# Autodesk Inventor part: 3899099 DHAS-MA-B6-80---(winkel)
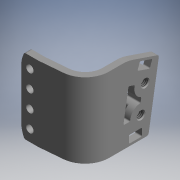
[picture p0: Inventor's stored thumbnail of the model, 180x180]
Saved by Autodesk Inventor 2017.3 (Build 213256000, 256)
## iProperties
Part Number: 3899099 DHAS-MA-B6-80---(winkel)
Material: Generic
Catalog Web Link: www.cadenas.de
Description: DHAS-MA_w-bracket
Vendor: FESTO
Document SubType Name: Modeling
Designer: partserver
Manufacturer: FESTO
Mass: 5.29381 g
Surface Area: 44.3897 cm^2
Volume: 5.29381 cm^3
Density: 1 g/cm^3
Appearance: PSOLRGB-175-175-175
Category: PARTsolutions
Company: FESTO
Title: 3899099 DHAS-MA-B6-80---(winkel)
Author: Cadenas PARTsolutions
Comments: bracket
PSOL_IDENT_0: {$CADENAS_DATA\23d-libs\festo\parts\d\dhas\parts\dhas_ma_winkel.prj},208 {VTYP=3D},{NB=3899099 DHAS-
PSOL_IDENT_1: MA-B6-80---(winkel)},{LINA=3899099 DHAS-MA-B6-80---(winkel)},{NN=DHAS-MA_w},{DATE=30.08.2019 14:48:2
PSOL_IDENT_2: 6},{GEOMDATE=01.09.2017 11:45:00},{VERSION=},{LINEID=230},{WBVAR=},{WBNUMERIC=}  {NB=3899099 DHAS-MA
PSOL_IDENT_3: -B6-80---(winkel)},{LINA=3899099 DHAS-MA-B6-80---(winkel)},{KT=DUMMY},{TNR=3899099},{TYP=DHAS-MA-B6-
PSOL_IDENT_4: 80},{SIZE=80}
NB: 3899099 DHAS-MA-B6-80---(winkel)
NN: DHAS-MA_w
NT: bracket
NBSYN: $TNR. $TYP.---(winkel)
LINA: 3899099 DHAS-MA-B6-80---(winkel)
CATALOG: Festo
TNR: 3899099
TYP: DHAS-MA-B6-80
SIZE: 80
SUPPLIER: FESTO
ARTICLENO: 3899099 DHAS-MA-B6-80---(winkel)
BOMINFO: 3899099 DHAS-MA-B6-80---(winkel)
CREATOR: CADENAS GmbH
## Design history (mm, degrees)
sketch "Sketch_3"
  geometry: L1 (0, 1.811)-(20.7, 0); L2 (20.7, 0)-(28.6, 0); L3 (28.6, 0)-(28.6, 3); L4 (28.6, 3)-(20.7, 3); L5 (20.7, 3)-(3, 4.549); L6 (3, 4.549)-(3, 35); L7 (3, 35)-(0, 35); L8 (0, 35)-(0, 1.811)
  constraints: 16 end point
extrude "Extrusion1" join sketch "Sketch_3" distance "d0" = 34.5; taper "d1" = 0 deg
sketch "Sketch_2"
  geometry: L1 (0, 1.811)-(20.7, 0); L2 (20.7, 0)-(28.6, 0); L3 (28.6, 0)-(28.6, 3); L4 (28.6, 3)-(21.049, 3); L5 (20.352, 3.03)-(10.303, 3.91); L6 (3, 11.879)-(3, 35); L7 (3, 35)-(0, 35); L8 (0, 35)-(0, 1.811); A1 r 8 centre (21.049, 11) between (20.352, 3.03) and (21.049, 3); A2 r 8 centre (11, 11.879) between (3, 11.879) and (10.303, 3.91)
  constraints: 16 end point, 4 point on circle, 2 centre point
extrude "Extrusion2" join sketch "Sketch_2" distance "d2" = 34.5; taper "d3" = 0 deg
sketch "Sketch_4"
  geometry: L1 (-5, -5)-(35, -5); L2 (35, -5)-(35, 45); L3 (35, 45)-(-5, 45); L4 (-5, 45)-(-5, -5); L5 (10.041, 0.933)-(20.222, 0.042); L6 (21.18, 0)-(28.6, 0); L7 (28.6, 0)-(28.6, 3); L8 (28.6, 3)-(21.049, 3); L9 (20.352, 3.03)-(10.303, 3.91); L10 (3, 11.879)-(3, 35); L11 (3, 35)-(0, 35); L12 (0, 35)-(0, 11.891); A1 r 11 centre (11, 11.891) between (0, 11.891) and (10.041, 0.933); A2 r 11 centre (21.18, 11) between (20.222, 0.042) and (21.18, 0); A3 r 8 centre (21.049, 11) between (20.352, 3.03) and (21.049, 3); A4 r 8 centre (11, 11.879) between (3, 11.879) and (10.303, 3.91)
  constraints: 24 end point, 8 point on circle, 4 centre point
extrude "Extrusion3" cut sketch "Sketch_4" distance "d4" = 48; taper "d5" = 0 deg
sketch "Sketch_5"
  geometry: L1 (45, 55)-(-5, 55); L2 (-5, 55)-(-5, -5); L3 (-5, -5)-(45, -5); L4 (45, -5)-(45, 55); L5 (29.252, 34.5)-(0, 34.5); L6 (0, 34.5)-(0, 0); L7 (0, 0)-(18.13, 0); L8 (22.939, 0.792)-(34.195, 4.602); L9 (34.861, 5.712)-(30.238, 33.663); A1 r 15 centre (18.13, 15) between (18.13, 0) and (22.939, 0.792); A2 r 1 centre (33.875, 5.549) between (34.195, 4.602) and (34.861, 5.712); A3 r 1 centre (29.252, 33.5) between (30.238, 33.663) and (29.252, 34.5)
  constraints: 18 end point, 6 point on circle, 3 centre point
extrude "Extrusion4" cut sketch "Sketch_5" distance "d6" = 3; taper "d7" = 0 deg
sketch "Sketch_6"
  geometry: L1 (5, 53)-(-35, 53); L2 (-35, 53)-(-35, -5); L3 (-35, -5)-(5, -5); L4 (5, -5)-(5, 53); L5 (0, 34.5)-(-26.483, 34.5); L6 (-28.6, 28.5)-(-28.6, 6); L7 (-26.483, 0)-(0, 0); L8 (0, 0)-(0, 34.5); A1 r 1 centre (-26.483, 33.5) between (-26.483, 34.5) and (-27.388, 33.926); A2 r 12.75 centre (-15.85, 28.5) between (-27.388, 33.926) and (-28.6, 28.5); A3 r 12.75 centre (-15.85, 6) between (-28.6, 6) and (-27.388, 0.574); A4 r 1 centre (-26.483, 1) between (-27.388, 0.574) and (-26.483, 0)
  constraints: 16 end point, 8 point on circle, 4 centre point
extrude "Extrusion5" cut sketch "Sketch_6" distance "d8" = 3; taper "d9" = 0 deg
sketch "Sketch6"
  geometry: 1 further point
hole "Hole1" sketch "Sketch6" at (3.42, 29.25) diameter "d10" = 3.4; stored, may be unused: countersink angle "d14" = 90 deg, drill point angle "d16" = 0 deg; dims "d11" = 6, "d12" = 4, "d13" = 2, "d15" = 3
pattern_linear "Rectangular Pattern1" dims "d19" = 8, "d22" = 0
sketch "Sketch_10"
  geometry: L1 (30.244, 8.053)-(25.51, 6.442); L2 (25.198, 5.808)-(26.003, 3.441); L3 (26.638, 3.129)-(31.371, 4.74); L4 (31.683, 5.374)-(30.878, 7.741); A1 r 0.5 centre (30.405, 7.58) between (30.878, 7.741) and (30.244, 8.053); A2 r 0.5 centre (25.671, 5.969) between (25.51, 6.442) and (25.198, 5.808); A3 r 0.5 centre (26.477, 3.602) between (26.003, 3.441) and (26.638, 3.129); A4 r 0.5 centre (31.21, 5.213) between (31.371, 4.74) and (31.683, 5.374)
  constraints: 8 end point, 8 point on circle, 4 centre point
extrude "Extrusion6" cut sketch "Sketch_10" distance "d23" = 3; taper "d24" = 0 deg
sketch "Sketch_18"
  geometry: L1 (21.121, 32.96)-(21.121, 30.46); L2 (21.621, 29.96)-(26.621, 29.959); L3 (27.121, 30.459)-(27.121, 32.959); L4 (26.621, 33.459)-(21.621, 33.46); A1 r 0.5 centre (21.621, 32.96) between (21.621, 33.46) and (21.121, 32.96); A2 r 0.5 centre (21.621, 30.46) between (21.121, 30.46) and (21.621, 29.96); A3 r 0.5 centre (26.621, 30.459) between (26.621, 29.959) and (27.121, 30.459); A4 r 0.5 centre (26.621, 32.959) between (27.121, 32.959) and (26.621, 33.459)
  constraints: 8 end point, 8 point on circle, 4 centre point
extrude "Extrusion7" cut sketch "Sketch_18" distance "d25" = 3; taper "d26" = 0 deg
sketch "Sketch_12"
  geometry: L1 (21.161, 24.787)-(19.119, 24.785); L2 (18.626, 24.204)-(20.822, 10.928); L3 (21.476, 10.536)-(23.409, 11.192); L4 (26.746, 18.009)-(26.515, 19.407); A1 r 0.5 centre (19.12, 24.285) between (19.119, 24.785) and (18.626, 24.204); A2 r 0.5 centre (21.315, 11.009) between (20.822, 10.928) and (21.476, 10.536); A3 r 0.5 centre (23.249, 11.665) between (23.409, 11.192) and (23.735, 11.782); A4 r 5 centre (28.596, 12.952) between (26.466, 17.475) and (23.735, 11.782); A5 r 0.5 centre (26.253, 17.927) between (26.466, 17.475) and (26.746, 18.009); A6 r 0.5 centre (26.022, 19.325) between (26.515, 19.407) and (26.078, 19.822); A7 r 5 centre (26.638, 24.791) between (21.659, 24.333) and (26.078, 19.822); A8 r 0.5 centre (21.161, 24.287) between (21.659, 24.333) and (21.161, 24.787)
  constraints: 16 point on circle, 8 centre point, 8 end point
extrude "Extrusion8" cut sketch "Sketch_12" distance "d27" = 3; taper "d28" = 0 deg
sketch "Sketch_20"
  geometry: L1 (-27.792, 22.594)-(-21.139, 23.694); L2 (-19.407, 26.515)-(-18.009, 26.746); L3 (-15.461, 24.633)-(-8.808, 25.734); L4 (-8.025, 27.043)-(-9.657, 31.84); L5 (-10.767, 32.505)-(-18.316, 31.256); L6 (-18.966, 30.642)-(-19.755, 30.512); L7 (-20.569, 30.884)-(-28.118, 29.635); L8 (-28.954, 28.649)-(-28.955, 23.581); A1 r 1 centre (-27.955, 23.581) between (-28.955, 23.581) and (-27.792, 22.594); A2 r 1 centre (-21.302, 24.681) between (-21.139, 23.694) and (-20.43, 24.192); A3 r 5 centre (-24.791, 26.638) between (-20.43, 24.192) and (-19.822, 26.078); A4 r 0.5 centre (-19.325, 26.022) between (-19.407, 26.515) and (-19.822, 26.078); A5 r 0.5 centre (-17.927, 26.253) between (-17.475, 26.466) and (-18.009, 26.746); A6 r 5 centre (-12.952, 28.596) between (-17.475, 26.466) and (-16.292, 24.876); A7 r 1 centre (-15.624, 25.62) between (-16.292, 24.876) and (-15.461, 24.633); A8 r 1 centre (-8.971, 26.72) between (-8.808, 25.734) and (-8.025, 27.043); A9 r 1 centre (-10.604, 31.518) between (-9.657, 31.84) and (-10.767, 32.505); A10 r 0.4 centre (-18.251, 30.862) between (-18.316, 31.256) and (-18.641, 30.949); A11 r 0.4 centre (-19.031, 31.037) between (-18.966, 30.642) and (-18.641, 30.949); A12 r 0.4 centre (-19.821, 30.906) between (-20.162, 30.698) and (-19.755, 30.512); A13 r 0.4 centre (-20.503, 30.489) between (-20.162, 30.698) and (-20.569, 30.884); A14 r 1 centre (-27.954, 28.649) between (-28.118, 29.635) and (-28.954, 28.649)
  constraints: 28 point on circle, 16 end point, 14 centre point
extrude "Extrusion9" join sketch "Sketch_20" distance "d29" = 3; taper "d30" = 0 deg
sketch "Sketch_13"
  geometry: L1 (6, -9.014)-(0, -9.014); L2 (0, -9.014)-(0, -7.014); L3 (0, -7.014)-(0.379, -7.393); L4 (0.379, -7.393)-(5.621, -7.393); L5 (5.621, -7.393)-(6, -7.014); L6 (6, -7.014)-(6, -9.014); L7 (6, -9.014)-(0, -9.014)
  constraints: 14 end point
revolve "Revolution1" sketch "Sketch_13" stored, may be unused: angle "d31" = 360 deg
thread "Thread1" dims "d32" = 5.242, "d33" = 0
sketch "Sketch_14"
  geometry: L1 (6, -21.014)-(0, -21.014); L2 (0, -21.014)-(0, -19.014); L3 (0, -19.014)-(0.379, -19.393); L4 (0.379, -19.393)-(5.621, -19.393); L5 (5.621, -19.393)-(6, -19.014); L6 (6, -19.014)-(6, -21.014); L7 (6, -21.014)-(0, -21.014)
  constraints: 14 end point
revolve "Revolution2" sketch "Sketch_14" stored, may be unused: angle "d34" = 360 deg
thread "Thread2" dims "d35" = 5.242, "d36" = 0
node "ANBAU_XY"
node "ANBAU_YZ"
node "ANBAU_ZX"
node "ANBAU_X"
node "ANBAU_Y"
node "ANBAU_Z"
node "ANBAU_Center"
node "DIN912_1_XY"
node "DIN912_1_YZ"
node "DIN912_1_ZX"
node "DIN912_1_X"
node "DIN912_1_Y"
node "DIN912_1_Z"
node "DIN912_1_Center"
node "DIN912_2_XY"
node "DIN912_2_YZ"
node "DIN912_2_ZX"
node "DIN912_2_X"
node "DIN912_2_Y"
node "DIN912_2_Z"
node "DIN912_2_Center"
node "DIN912_3_XY"
node "DIN912_3_YZ"
node "DIN912_3_ZX"
node "DIN912_3_X"
node "DIN912_3_Y"
node "DIN912_3_Z"
node "DIN912_3_Center"
body "Solid1"
other parameters: "d37" = 0, "d38" = 0, "d39" = 0, "d40" = 0
